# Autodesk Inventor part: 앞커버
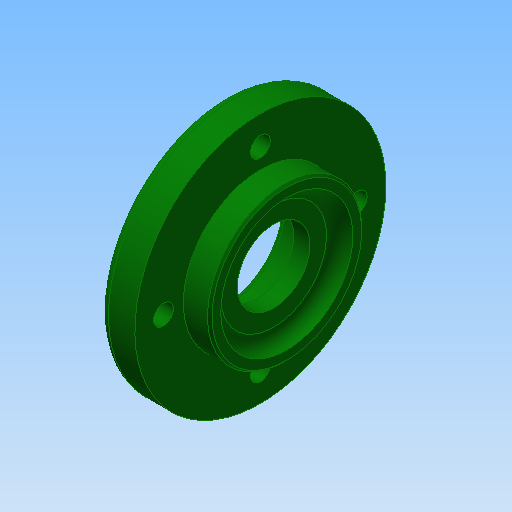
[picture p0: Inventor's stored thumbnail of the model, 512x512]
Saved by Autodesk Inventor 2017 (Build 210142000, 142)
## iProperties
Created: 2015-12
Part Number: 앞커버
Material: 알루미늄 6061
Document SubType Name: Modeling
Designer: mduedu
Density: 2.71 g/cm^3
Appearance: 진녹색
Author: mduedu
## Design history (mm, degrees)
sketch "스케치1"
  geometry: L1 (0, 0)-(14, 0); L2 (14, 0)-(14, 17.5); L3 (14, 17.5)-(8, 17.5); L4 (8, 17.5)-(8, 28.5); L5 (8, 28.5)-(0, 28.5); L6 (0, 28.5)-(0, 0)
  constraints: 12 end point, 4 parallel, 1 horizontal, 1 perpendicular
  dimensions: "d0" = 14 distance between parallel lines of L2 L6; "d2" = 8 distance of L4.end L5.end; "d3" = 57 diameter of L5 L1; "d4" = 35 diameter of L3 L1
revolve "회전1" sketch "스케치1" stored, may be unused: angle "d5" = 90 deg
hole "구멍1" diameter "d8" = 30; stored, may be unused: countersink angle "d12" = 90 deg, drill point angle "d14" = 0 deg; dims "d6" = 10, "d7" = 10, "d9" = 6, "d10" = 4, "d11" = 2, "d13" = 3
hole "구멍2" diameter "d17" = 25; stored, may be unused: countersink angle "d21" = 90 deg, drill point angle "d23" = 0 deg; dims "d15" = 10, "d16" = 10, "d18" = 6, "d19" = 4, "d20" = 2, "d22" = 7.3
hole "구멍3" diameter "d26" = 16.5; stored, may be unused: countersink angle "d30" = 90 deg, drill point angle "d32" = 0 deg; dims "d24" = 10, "d25" = 10, "d27" = 6, "d28" = 4, "d29" = 2, "d31" = 7.3
fillet "모깎기1" dims "d33" = 0.3
chamfer "모따기1" distance "d34" = 1; stored, may be unused: second distance "d35" = 2, angle "d36" = 30 deg
fillet "모깎기2" dims "d37" = 3
fillet "모깎기3" dims "d38" = 2
chamfer "모따기2" distance "d39" = 0.5; stored, may be unused: second distance "d40" = 2, angle "d41" = 45 deg
sketch "스케치2" dims "d42" = 42
  geometry: 9 further points
  constraints: 3 coincident, 2 vertical alignment, 9 other
  dimensions: "d46" = 360 deg dimension on point (0, 0) point (0, 21) (derived)
sketch "스케치3" dims "d57" = 44
  geometry: C1 r 13.077 at (0, 0) reference; C2 r 26.5 at (0, 0) reference; 5 further points
  constraints: 3 horizontal alignment, 1 coincident, 1 vertical alignment, 2 other
hole "구멍4" sketch "스케치3" at (-22, 0), (0, -22), (22, 0), (0, 22) diameter "d50" = 4.5; stored, may be unused: countersink angle "d54" = 90 deg, drill point angle "d56" = 0 deg; dims "d51" = 6, "d52" = 8, "d53" = 4.6, "d55" = 8
node "솔리드1"
